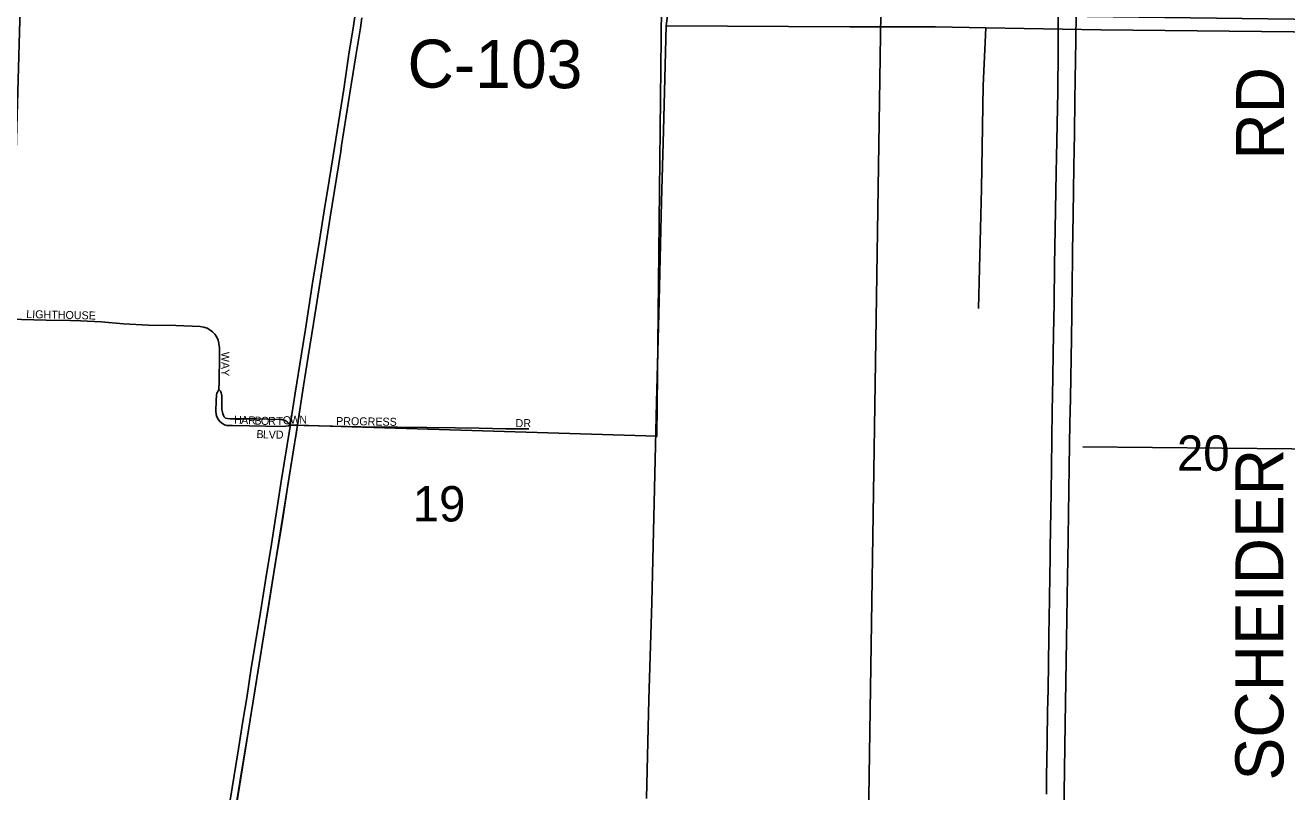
# Model space of a CAD drawing. Extents: x -5.6 to 34, y 0 to 22.
# Drawn here: x 3.152 to 6.304, y 14.869 to 16.786 of the extents above; entities that cross this region are included whole.
import ezdxf

# ---------------------------------------------------------------- set-up
doc = ezdxf.new("R2010")
doc.units = 0
for name, color, linetype in [('GM_X_City_Street', 7, 'Continuous'), ('GM_X_City_Street_Text', 7, 'Continuous'), ('GM_X_Corporation', 7, 'Continuous'), ('GM_X_County_Road_Text', 7, 'Continuous'), ('GM_X_Interstate_Route', 7, 'Continuous'), ('GM_X_Minor_River', 7, 'Continuous'), ('GM_X_Section', 7, 'Continuous'), ('GM_X_Section_Text', 7, 'Continuous'), ('GM_X_State_Route', 7, 'Continuous'), ('GM_X_Township_Road_Text', 7, 'Continuous')]:
    doc.layers.add(name, color=color, linetype=linetype)

msp = doc.modelspace()

# ---------------------------------------------------------------- linework, layer by layer
at = {"layer": 'GM_X_City_Street'}
for points in [[(3.0561, 16.0534), (3.0804, 16.0522), (3.142, 16.0502), (3.204, 16.0486), (3.2645, 16.0479), (3.2908, 16.0467), (3.3413, 16.0441), (3.3969, 16.0389), (3.4598, 16.0363), (3.5281, 16.0348), (3.5886, 16.0324), (3.598, 16.031), (3.6058, 16.0284), (3.6131, 16.0246), (3.6195, 16.0195), (3.625, 16.0134), (3.6302, 16.0055), (3.6336, 15.9981), (3.6357, 15.9902), (3.637, 15.9795), (3.6371, 15.9583), (3.636, 15.8939), (3.6356, 15.8747)], [(3.6356, 15.8747), (3.6334, 15.8721), (3.6317, 15.8687), (3.6306, 15.8656), (3.6296, 15.8612), (3.6285, 15.8468), (3.6281, 15.8219), (3.629, 15.8128), (3.6307, 15.8064), (3.6335, 15.8005), (3.6375, 15.7953), (3.6418, 15.7915), (3.6467, 15.7886)], [(3.6356, 15.8747), (3.6375, 15.8729), (3.6395, 15.8707), (3.6405, 15.8689), (3.6413, 15.8668), (3.6423, 15.863), (3.6427, 15.859), (3.6428, 15.8524), (3.643, 15.8327), (3.6432, 15.825), (3.6442, 15.8181), (3.645, 15.8143), (3.6469, 15.8097), (3.6484, 15.8066), (3.6502, 15.8048), (3.6523, 15.8032)], [(3.6523, 15.8032), (3.6566, 15.8027), (3.6649, 15.8021), (3.7267, 15.8014), (3.7886, 15.8004), (3.793, 15.7998), (3.7977, 15.7986), (3.8015, 15.7972), (3.8059, 15.7942), (3.8104, 15.7904), (3.8137, 15.786)], [(3.6467, 15.7886), (3.6499, 15.7871), (3.6552, 15.7854), (3.6609, 15.7847), (3.6695, 15.7847), (3.7531, 15.7833), (3.7953, 15.7829), (3.8024, 15.7833), (3.8091, 15.7843), (3.8137, 15.786)], [(3.8137, 15.786), (3.8322, 15.7856)], [(3.8322, 15.7856), (3.8483, 15.7852), (3.9911, 15.7815), (4.0828, 15.7806), (4.1549, 15.7799), (4.2269, 15.7791), (4.2859, 15.7783), (4.3514, 15.777), (4.4103, 15.7765)]]:
    msp.add_lwpolyline(points, dxfattribs=at)
at = {"layer": 'GM_X_Corporation'}
msp.add_lwpolyline([(3.6566, 14.6969), (3.8322, 15.7856), (4.7302, 15.7581), (4.7414, 16.8317)], dxfattribs=at)
at = {"layer": 'GM_X_Interstate_Route'}
for points in [[(5.7034, 14.8634), (5.704, 14.912), (5.7044, 14.9449), (5.705, 14.9974), (5.7064, 15.0696), (5.7075, 15.1247), (5.7098, 15.256), (5.7105, 15.3112), (5.711, 15.344), (5.7121, 15.4175), (5.7125, 15.4438), (5.713, 15.4779), (5.7144, 15.5711), (5.7151, 15.6184), (5.7161, 15.6801), (5.7182, 15.8232), (5.7187, 15.8587), (5.7195, 15.9086), (5.7205, 15.9637), (5.7215, 16.0123), (5.7227, 16.0898), (5.724, 16.1882), (5.7248, 16.2289), (5.7281, 16.418), (5.7287, 16.4561), (5.7317, 16.6202), (5.7332, 16.7226), (5.7328, 16.8156)], [(5.745, 14.6938), (5.7503, 15.0391), (5.7536, 15.2492), (5.7563, 15.4093), (5.7568, 15.4474), (5.7603, 15.6811), (5.7622, 15.7914), (5.7627, 15.8203), (5.7632, 15.8544), (5.7657, 16.0028), (5.7668, 16.0645), (5.768, 16.1472), (5.7685, 16.1944), (5.7689, 16.2207), (5.7699, 16.3126), (5.7707, 16.3717), (5.7717, 16.4321), (5.7732, 16.5148), (5.7746, 16.5989), (5.7769, 16.7485), (5.7776, 16.8149)]]:
    msp.add_lwpolyline(points, dxfattribs=at)
at = {"layer": 'GM_X_Minor_River'}
for points in [[(5.0409, 18.1292), (5.0324, 18.0083), (5.0229, 17.8778), (4.9096, 17.8805), (4.9022, 17.7403), (4.893, 17.5609), (4.8761, 17.4578), (4.8454, 17.3118), (4.8223, 17.1808), (4.7956, 17.0363), (4.7703, 16.9158), (4.7536, 16.7847), (4.7464, 16.5218), (4.7413, 16.3446), (4.7361, 16.0969), (4.7291, 15.8428), (4.723, 15.5919), (4.717, 15.3426), (4.7103, 15.0997), (4.7043, 14.852)], [(4.7536, 16.7847), (5.2118, 16.7815), (5.4263, 16.7816)], [(5.4263, 16.7816), (5.5524, 16.7792), (5.8395, 16.774), (6.3206, 16.7696), (6.7649, 16.7624), (7.1996, 16.7586), (7.4222, 16.7566), (7.6894, 16.7524)], [(5.5337, 16.0773), (5.5408, 16.3778), (5.5457, 16.635), (5.5524, 16.7792)], [(5.7948, 15.7318), (6.3166, 15.7268), (6.6149, 15.7247), (6.6149, 15.2374)]]:
    msp.add_lwpolyline(points, dxfattribs=at)
at = {"layer": 'GM_X_Section'}
for points in [[(3.1401, 16.8587), (5.2895, 16.8144), (5.2575, 14.6921), (3.0791, 14.7168)], [(5.2895, 16.8144), (7.4183, 16.7871), (7.3798, 14.6657), (5.2575, 14.6921)]]:
    msp.add_lwpolyline(points, close=True, dxfattribs=at)
at = {"layer": 'GM_X_State_Route'}
for points in [[(3.6571, 14.8082), (3.6685, 14.8787), (3.6843, 14.9763), (3.6952, 15.0459), (3.705, 15.1038), (3.7164, 15.1781), (3.7369, 15.3025), (3.7546, 15.4134), (3.7649, 15.4774), (3.7912, 15.6449), (3.8132, 15.7825), (3.8137, 15.786), (3.8265, 15.8659), (3.842, 15.9646), (3.8518, 16.0258), (3.8688, 16.1356), (3.887, 16.2477), (3.8989, 16.3221), (3.9107, 16.3976), (3.9209, 16.4589), (3.9474, 16.6263), (3.9603, 16.7134), (3.9719, 16.7847), (3.9806, 16.8404)], [(3.9661, 16.6372), (3.9775, 16.7095), (3.9891, 16.7795), (3.993, 16.8041)], [(3.9398, 16.4702), (3.9422, 16.4851), (3.9652, 16.6316), (3.9661, 16.6372)], [(3.8275, 15.7584), (3.8322, 15.7856), (3.8364, 15.8131), (3.8472, 15.8846), (3.8589, 15.9572), (3.8718, 16.0402), (3.8885, 16.1452), (3.9137, 16.3061), (3.9398, 16.4702)], [(3.7788, 15.4529), (3.7883, 15.5115), (3.7957, 15.5582), (3.8078, 15.6361), (3.826, 15.7502), (3.8275, 15.7584)], [(3.7135, 15.0489), (3.7137, 15.05), (3.726, 15.1265), (3.7381, 15.199), (3.7522, 15.2872), (3.7595, 15.3313), (3.7697, 15.3961), (3.7772, 15.4428), (3.7788, 15.4529)], [(3.6566, 14.6969), (3.6754, 14.8154), (3.6887, 14.8984), (3.7135, 15.0489)]]:
    msp.add_lwpolyline(points, dxfattribs=at)

# ---------------------------------------------------------------- texts
at = {"layer": 'GM_X_City_Street_Text'}
for s, rotation, p in [('LIGHTHOUSE', 358.7115, (3.1539, 16.0538)), ('WAY', 270, (3.6415, 15.9691)), ('H', 357.5294, (3.6731, 15.7898)), ('A', 357.5158, (3.6907, 15.7891)), ('R', 357.5341, (3.7083, 15.7883)), ('B', 357.5341, (3.7241, 15.7876)), ('O', 358.2026, (3.7402, 15.7869)), ('R', 359.8279, (3.7584, 15.7864)), ('T', 0.6284, (3.7798, 15.7864)), ('O', 8.5816, (3.7969, 15.7868)), ('W', 1.177, (3.8136, 15.7894)), ('N', 0, (3.8364, 15.7898)), ('PROGRESS', 359.1803, (3.9283, 15.7863)), ('DR', 0, (4.3769, 15.781)), ('B', 356.0389, (3.7288, 15.7541)), ('L', 358.0978, (3.7453, 15.753)), ('V', 359.2858, (3.7599, 15.7525)), ('D', 359.9688, (3.7777, 15.7523))]:
    msp.add_text(s, height=0.02, rotation=rotation, dxfattribs=at).set_placement(p)
at = {"layer": 'GM_X_County_Road_Text'}
msp.add_text('C-103', height=0.12, rotation=359.7293, dxfattribs=at).set_placement((4.1066, 16.6301))
at = {"layer": 'GM_X_Section_Text'}
for s, p in [('20', (6.0296, 15.6718)), ('19', (4.12, 15.5451))]:
    msp.add_text(s, height=0.0884, rotation=0, dxfattribs=at).set_placement(p)
at = {"layer": 'GM_X_Township_Road_Text'}
for s, p in [('RD', (6.2974, 16.4496)), ('SCHEIDER', (6.2956, 14.8973))]:
    msp.add_text(s, height=0.12, rotation=90, dxfattribs=at).set_placement(p)

doc.saveas('drawing.dxf')
